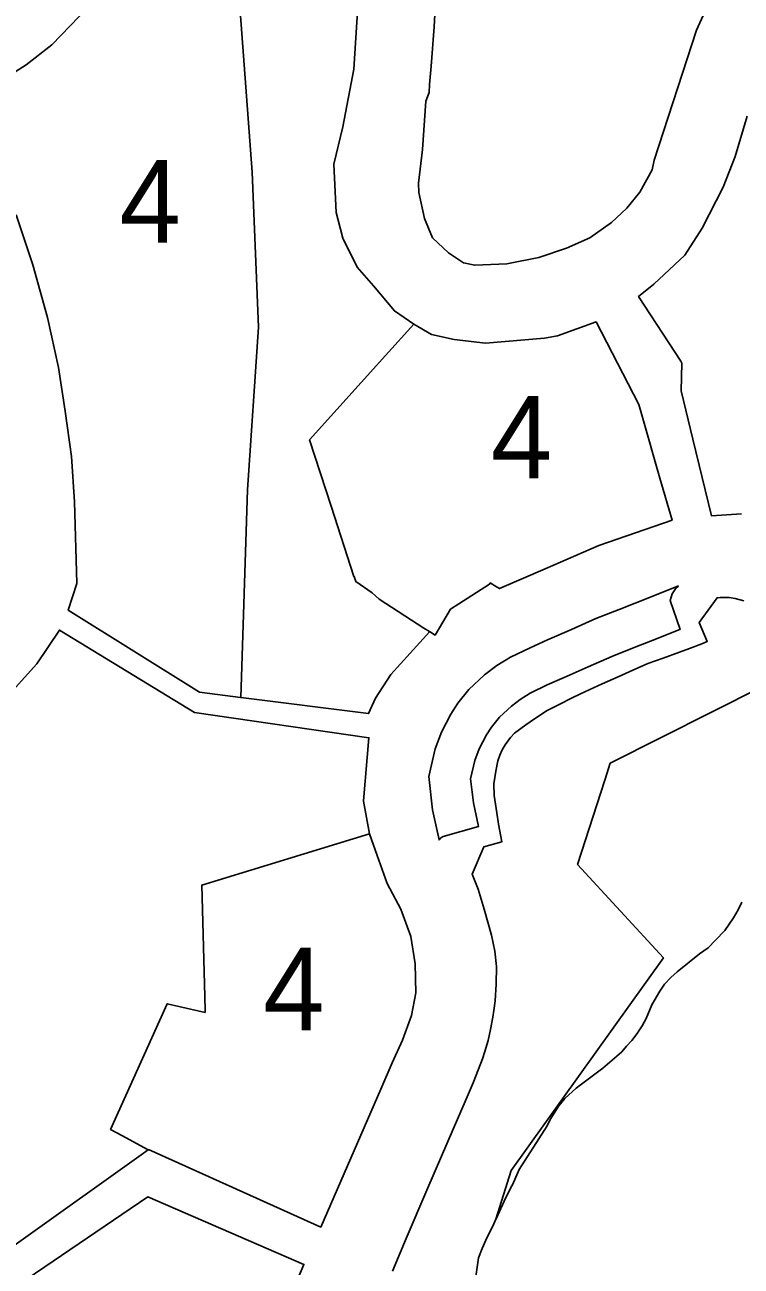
# Model space of a CAD drawing. Extents: x 598968 to 613553, y 4409678 to 4430833.
# Drawn here: x 610612.2 to 610716.3, y 4416399.9 to 4416580.3 of the extents above; entities that cross this region are included whole.
import ezdxf

# ---------------------------------------------------------------- set-up
doc = ezdxf.new("R2010")
doc.units = 0
doc.layers.add('1', color=7, linetype='Continuous')
doc.layers.add('ZONA 4. CASES UNIFAMILIRAS AÏLLADES EN PARCEL.LES', color=7, linetype='Continuous')

msp = doc.modelspace()

# ---------------------------------------------------------------- linework, layer by layer
at = {"layer": '1'}
for points in [[(610660.9172, 4416587.5407), (610660.0579, 4416573.8288), (610658.4675, 4416565.4121), (610657.1735, 4416560.0312), (610657.1748, 4416560.0035), (610657.1735, 4416559.9982), (610657.4965, 4416552.9968), (610658.4664, 4416549.2357), (610660.5543, 4416545.0335), (610662.9194, 4416542.3407), (610665.9554, 4416538.6825), (610668.7515, 4416536.7719), (610668.7939, 4416536.7578), (610671.3454, 4416535.2616), (610674.6182, 4416534.5411), (610679.1944, 4416533.987), (610687.7415, 4416534.7319), (610689.6651, 4416535.0746), (610695.254, 4416537.0816), (610701.4865, 4416525.0936), (610702.0527, 4416523.0575), (610704.5314, 4416514.3787), (610706.2986, 4416508.3056), (610695.6807, 4416504.6208), (610687.8593, 4416501.2363), (610681.2337, 4416498.3494), (610680.5348, 4416498.7445), (610680.2391, 4416498.9415), (610679.8813, 4416499.1721), (610679.7915, 4416498.984), (610675.3271, 4416496.14), (610674.0967, 4416495.355), (610671.8547, 4416491.5958), (610671.0654, 4416492.1057), (610671.0443, 4416492.0863), (610671.0281, 4416492.0685), (610665.4224, 4416485.867), (610663.2043, 4416482.4376), (610662.2097, 4416480.1888), (610643.6531, 4416482.5219), (610643.6115, 4416482.5122), (610637.6424, 4416483.3016), (610618.5505, 4416495.1884), (610618.5594, 4416495.2159), (610619.8116, 4416499.0925), (610619.8107, 4416499.1227), (610619.8116, 4416499.1255), (610619.4525, 4416510.9441), (610619.0127, 4416517.5269), (610618.1214, 4416524.1063), (610617.1325, 4416530.4638), (610615.5494, 4416537.7554), (610613.4179, 4416545.3677), (610610.9893, 4416552.6588)], [(610643.1815, 4416586.8512), (610645.2816, 4416558.8517), (610646.2116, 4416536.342), (610644.6019, 4416512.6772), (610643.6531, 4416482.5219), (610662.2097, 4416480.1888), (610663.2043, 4416482.4376), (610665.4224, 4416485.867), (610671.0281, 4416492.0685), (610671.0443, 4416492.0863), (610670.2384, 4416492.6069), (610663.7445, 4416496.8021), (610662.6969, 4416497.7491), (610660.3443, 4416499.3532), (610660.11, 4416500.0876), (610660.072, 4416500.1219), (610656.762, 4416510.3217), (610653.632, 4416519.9615), (610664.6717, 4416532.1913), (610668.7939, 4416536.7578), (610668.7515, 4416536.7719), (610665.9554, 4416538.6825), (610662.9194, 4416542.3407), (610660.5543, 4416545.0335), (610658.4664, 4416549.2357), (610657.4965, 4416552.9968), (610657.1735, 4416559.9982), (610657.1748, 4416560.0035), (610657.1735, 4416560.0312), (610658.4675, 4416565.4121), (610660.0579, 4416573.8288), (610660.9172, 4416587.5407)], [(610712.5511, 4416585.5047), (610709.8711, 4416579.4847), (610703.7213, 4416560.5849), (610703.4213, 4416559.1949), (610701.6113, 4416555.945), (610699.7413, 4416553.625), (610697.5114, 4416551.5149), (610694.3714, 4416549.3149), (610690.9815, 4416547.8049), (610686.9615, 4416546.4348), (610682.2916, 4416545.5448), (610677.6316, 4416545.3246), (610676.0117, 4416545.6947), (610673.8317, 4416547.1146), (610671.5017, 4416549.3245), (610670.3118, 4416552.1045), (610669.5217, 4416555.8744), (610669.4628, 4416557.2699), (610670.0517, 4416562.1613), (610670.5417, 4416569.1511), (610671.0117, 4416570.4011), (610671.0486, 4416571.5732), (610671.2898, 4416574.2337), (610671.7388, 4416579.965), (610671.9916, 4416584.441)], [(610610.8425, 4416573.4031), (610612.4503, 4416574.4243), (610616.1822, 4416577.3684), (610621.454, 4416582.8233)], [(610716.3773, 4416509.2172), (610712.0135, 4416508.9309), (610709.3171, 4416520.0641), (610707.6145, 4416527.0938), (610707.6137, 4416527.0974), (610707.7303, 4416531.0838), (610707.7313, 4416531.1154), (610707.5513, 4416531.3954), (610701.4241, 4416540.7873), (610703.6731, 4416542.5836), (610708.1712, 4416546.7722), (610710.6912, 4416550.6882), (610713.7487, 4416556.6722), (610715.4893, 4416561.1421), (610717.2091, 4416566.9639)], [(610665.6539, 4416399.1727), (610667.6598, 4416403.911), (610670.642, 4416410.9433), (610673.7085, 4416418.014), (610676.3563, 4416424.1472), (610677.3794, 4416426.5437), (610678.1882, 4416428.4934), (610678.746, 4416430.0328), (610679.1044, 4416431.0824), (610679.5591, 4416432.6739), (610679.9119, 4416434.2831), (610680.2504, 4416436.0944), (610680.4054, 4416437.0505), (610680.6118, 4416438.4331), (610680.7221, 4416440.878), (610680.7918, 4416443.423), (610680.7911, 4416443.4297), (610680.7918, 4416443.4561), (610680.5518, 4416445.666), (610680.0618, 4416447.9959), (610678.9792, 4416451.7511), (610678.1418, 4416454.6559), (610677.2487, 4416456.839), (610678.9418, 4416460.8127), (610681.5418, 4416461.5228), (610681.5361, 4416461.5543), (610681.5418, 4416461.5558), (610681.0822, 4416464.1295), (610680.8146, 4416465.7756), (610680.4418, 4416468.2957), (610680.4025, 4416469.9571), (610680.4018, 4416469.9857), (610680.6818, 4416471.8356), (610681.0018, 4416473.2957), (610681.2817, 4416474.1156), (610681.6317, 4416474.9056), (610682.0517, 4416475.6556), (610682.8118, 4416476.7056), (610683.4017, 4416477.3356), (610685.0517, 4416478.5656), (610686.3269, 4416479.4131), (610688.1517, 4416480.6257), (610689.9703, 4416481.5548), (610691.6754, 4416482.4261), (610692.9952, 4416483.0446), (610696.1546, 4416484.5099), (610698.4499, 4416485.5234), (610700.046, 4416486.2249), (610702.8014, 4416487.4358), (610705.0072, 4416488.2487), (610707.3931, 4416489.1278), (610708.8302, 4416489.6575), (610710.6151, 4416490.3361), (610711.4094, 4416490.6611), (610711.4213, 4416490.6659), (610710.2601, 4416493.4151), (610712.8414, 4416497.0129), (610713.2813, 4416497.0529), (610713.585, 4416497.0483), (610714.6013, 4416497.033), (610715.4713, 4416496.913), (610716.7512, 4416496.563)], [(610716.7512, 4416496.563), (610715.4713, 4416496.913), (610714.6013, 4416497.033), (610713.585, 4416497.0483), (610713.2813, 4416497.0529), (610712.8414, 4416497.0129), (610710.2601, 4416493.4151), (610711.4213, 4416490.6659), (610711.4094, 4416490.6611), (610710.6151, 4416490.3361), (610708.8302, 4416489.6575), (610707.3931, 4416489.1278), (610705.0072, 4416488.2487), (610702.8014, 4416487.4358), (610700.046, 4416486.2249), (610698.4499, 4416485.5234), (610696.1546, 4416484.5099), (610692.9952, 4416483.0446), (610691.6754, 4416482.4261), (610689.9703, 4416481.5548), (610688.1517, 4416480.6257), (610686.3269, 4416479.4131), (610685.0517, 4416478.5656), (610683.4017, 4416477.3356), (610682.8118, 4416476.7056), (610682.0517, 4416475.6556), (610681.6317, 4416474.9056), (610681.2817, 4416474.1156), (610681.0018, 4416473.2957), (610680.6818, 4416471.8356), (610680.4018, 4416469.9857), (610680.4025, 4416469.9571), (610680.4418, 4416468.2957), (610680.8146, 4416465.7756), (610681.0822, 4416464.1295), (610681.5418, 4416461.5558), (610681.5361, 4416461.5543), (610681.5418, 4416461.5228), (610678.9418, 4416460.8127), (610677.2487, 4416456.839), (610678.1418, 4416454.6559), (610678.9792, 4416451.7511), (610680.0618, 4416447.9959), (610680.5518, 4416445.666), (610680.7918, 4416443.4561), (610680.7911, 4416443.4297), (610680.7918, 4416443.423), (610680.7221, 4416440.878), (610680.6118, 4416438.4331), (610680.4054, 4416437.0505), (610680.2504, 4416436.0944), (610679.9119, 4416434.2831), (610679.5591, 4416432.6739), (610679.1044, 4416431.0824), (610678.746, 4416430.0328), (610678.1882, 4416428.4934), (610677.3794, 4416426.5437), (610676.3563, 4416424.1472), (610673.7085, 4416418.014), (610670.642, 4416410.9433), (610667.6598, 4416403.911), (610665.6539, 4416399.1727)], [(610606.8922, 4416479.5621), (610613.976, 4416487.4297), (610617.2703, 4416492.3076), (610636.9174, 4416480.3426), (610662.2397, 4416476.6803), (610661.4697, 4416467.5107), (610661.4715, 4416467.5004), (610661.4697, 4416467.4776), (610662.3547, 4416462.7144), (610663.4643, 4416459.5728), (610664.9029, 4416455.4766), (610666.869, 4416451.7398), (610668.3335, 4416447.7964), (610668.9809, 4416443.8201), (610669.0539, 4416439.5933), (610668.431, 4416436.3144), (610667.1121, 4416432.7353), (610665.6495, 4416429.4534), (610663.9713, 4416425.6122), (610655.2382, 4416405.5775), (610630.2121, 4416416.8263), (610630.1857, 4416416.8075), (610610.6941, 4416402.8965)], [(610610.6941, 4416402.8965), (610630.1857, 4416416.8075), (610626.3636, 4416418.8744), (610624.7207, 4416419.7629), (610632.953, 4416438.0103), (610634.6035, 4416437.6375), (610638.4472, 4416436.7694), (610638.4407, 4416437.0122), (610638.3849, 4416439.0961), (610637.9529, 4416455.2452), (610662.3547, 4416462.7144), (610661.4697, 4416467.4776), (610661.4715, 4416467.5004), (610661.4697, 4416467.5107), (610662.2397, 4416476.6803), (610636.9174, 4416480.3426), (610617.2703, 4416492.3076), (610613.976, 4416487.4297), (610606.8922, 4416479.5621)], [(610677.5652, 4416396.7033), (610678.1938, 4416401.1172), (610678.7038, 4416402.4671), (610679.2138, 4416403.6871), (610680.4238, 4416406.067), (610680.7089, 4416406.7096), (610682.9414, 4416413.815), (610705.0415, 4416444.7155), (610692.5699, 4416458.2357), (610696.5349, 4416470.5118), (610697.3261, 4416472.9617), (610719.4516, 4416484.1178)], [(610719.4516, 4416484.1178), (610697.3261, 4416472.9617), (610696.5349, 4416470.5118), (610692.5699, 4416458.2357), (610705.0415, 4416444.7155), (610682.9414, 4416413.815), (610680.7089, 4416406.7096), (610680.7324, 4416406.7624), (610681.8838, 4416409.357), (610682.3437, 4416410.247), (610683.0237, 4416411.567), (610683.0937, 4416411.707), (610684.0636, 4416413.937), (610688.1336, 4416420.297), (610688.6035, 4416421.207), (610689.8335, 4416423.167), (610690.6934, 4416424.237), (610692.3734, 4416425.747), (610696.2333, 4416428.6569), (610698.2532, 4416430.417), (610698.9832, 4416431.037), (610699.6832, 4416431.837), (610700.4432, 4416432.697), (610701.2332, 4416433.697), (610701.4731, 4416434.067), (610701.9531, 4416434.807), (610702.5331, 4416435.867), (610703.373, 4416437.8769), (610704.513, 4416439.8669), (610705.203, 4416440.8569), (610706.123, 4416441.8369), (610707.033, 4416442.6569), (610710.2828, 4416445.267), (610711.5428, 4416446.167), (610712.5928, 4416447.247), (610713.9628, 4416448.647), (610715.2427, 4416450.517), (610715.9027, 4416451.647), (610716.4326, 4416452.757)], [(610612.604, 4416398.0546), (610630.0997, 4416409.9695), (610652.8129, 4416400.1541), (610652.8009, 4416400.1262), (610646.0374, 4416384.2133)]]:
    msp.add_lwpolyline(points, dxfattribs=at)
for points in [[(610672.6919, 4416462.1157), (610672.4516, 4416461.8292), (610671.5059, 4416466.2126), (610670.9433, 4416471.0291), (610671.8875, 4416475.0646), (610672.8002, 4416477.5035), (610674.1693, 4416480.0772), (610675.1898, 4416481.6806), (610676.7899, 4416483.6915), (610679.0616, 4416485.8197), (610680.8132, 4416487.1681), (610682.8351, 4416488.3971), (610685.6583, 4416489.7525), (610688.1945, 4416490.8767), (610691.672, 4416492.4181), (610695.218, 4416493.9902), (610698.6006, 4416495.3186), (610700.9597, 4416496.2452), (610707.1495, 4416498.6765), (610707.2167, 4416498.7029), (610706.9114, 4416498.4328), (610706.3314, 4416497.5728), (610706.0268, 4416496.6), (610707.4614, 4416492.3859), (610707.4516, 4416492.382), (610703.1531, 4416490.6937), (610700.7939, 4416489.7671), (610697.5315, 4416488.4857), (610694.1033, 4416486.9661), (610690.6259, 4416485.4247), (610688.1727, 4416484.3372), (610685.6986, 4416483.1493), (610684.2117, 4416482.2455), (610682.9517, 4416481.2755), (610681.2117, 4416479.6456), (610680.0818, 4416478.2256), (610679.3567, 4416477.0862), (610678.2818, 4416475.0656), (610677.6418, 4416473.3556), (610677.0218, 4416470.7056), (610677.0245, 4416470.6836), (610677.4318, 4416467.1956), (610678.1718, 4416463.7657), (610678.1651, 4416463.7638), (610673.0287, 4416462.3376)], [(610672.6919, 4416462.1157), (610673.0287, 4416462.3376), (610678.1651, 4416463.7638), (610678.1718, 4416463.7657), (610677.4318, 4416467.1956), (610677.0245, 4416470.6836), (610677.0218, 4416470.7056), (610677.6418, 4416473.3556), (610678.2818, 4416475.0656), (610679.3567, 4416477.0862), (610680.0818, 4416478.2256), (610681.2117, 4416479.6456), (610682.9517, 4416481.2755), (610684.2117, 4416482.2455), (610685.6986, 4416483.1493), (610688.1727, 4416484.3372), (610690.6259, 4416485.4247), (610694.1033, 4416486.9661), (610697.5315, 4416488.4857), (610700.7939, 4416489.7671), (610703.1531, 4416490.6937), (610707.4516, 4416492.382), (610707.4614, 4416492.3859), (610706.0268, 4416496.6), (610706.3314, 4416497.5728), (610706.9114, 4416498.4328), (610707.2167, 4416498.7029), (610707.1495, 4416498.6765), (610700.9597, 4416496.2452), (610698.6006, 4416495.3186), (610695.218, 4416493.9902), (610691.672, 4416492.4181), (610688.1945, 4416490.8767), (610685.6583, 4416489.7525), (610682.8351, 4416488.3971), (610680.8132, 4416487.1681), (610679.0616, 4416485.8197), (610676.7899, 4416483.6915), (610675.1898, 4416481.6806), (610674.1693, 4416480.0772), (610672.8002, 4416477.5035), (610671.8875, 4416475.0646), (610670.9433, 4416471.0291), (610671.5059, 4416466.2126), (610672.4516, 4416461.8292)]]:
    msp.add_lwpolyline(points, close=True, dxfattribs=at)
at = {"layer": 'ZONA 4. CASES UNIFAMILIRAS AÏLLADES EN PARCEL.LES'}
for points in [[(610610.9893, 4416552.6588), (610613.4179, 4416545.3677), (610615.5494, 4416537.7554), (610617.1325, 4416530.4638), (610618.1214, 4416524.1063), (610619.0127, 4416517.5269), (610619.4525, 4416510.9441), (610619.8116, 4416499.1255), (610619.8107, 4416499.1227), (610619.8116, 4416499.0925), (610618.5594, 4416495.2159), (610618.5505, 4416495.1884), (610637.6424, 4416483.3016), (610643.6115, 4416482.5122), (610643.6531, 4416482.5219), (610644.6019, 4416512.6772), (610646.2116, 4416536.342), (610645.2816, 4416558.8517), (610643.1815, 4416586.8512)], [(610671.9916, 4416584.441), (610671.7388, 4416579.965), (610671.2898, 4416574.2337), (610671.0486, 4416571.5732), (610671.0117, 4416570.4011), (610670.5417, 4416569.1511), (610670.0517, 4416562.1613), (610669.4628, 4416557.2699), (610669.5217, 4416555.8744), (610670.3118, 4416552.1045), (610671.5017, 4416549.3245), (610673.8317, 4416547.1146), (610676.0117, 4416545.6947), (610677.6316, 4416545.3246), (610682.2916, 4416545.5448), (610686.9615, 4416546.4348), (610690.9815, 4416547.8049), (610694.3714, 4416549.3149), (610697.5114, 4416551.5149), (610699.7413, 4416553.625), (610701.6113, 4416555.945), (610703.4213, 4416559.1949), (610703.7213, 4416560.5849), (610709.8711, 4416579.4847), (610712.5511, 4416585.5047)], [(610621.454, 4416582.8233), (610616.1822, 4416577.3684), (610612.4503, 4416574.4243), (610610.8425, 4416573.4031)], [(610717.2091, 4416566.9639), (610715.4893, 4416561.1421), (610713.7487, 4416556.6722), (610710.6912, 4416550.6882), (610708.1712, 4416546.7722), (610703.6731, 4416542.5836), (610701.4241, 4416540.7873), (610707.5513, 4416531.3954), (610707.7313, 4416531.1154), (610707.7303, 4416531.0838), (610707.6137, 4416527.0974), (610707.6145, 4416527.0938), (610709.3171, 4416520.0641), (610712.0135, 4416508.9309), (610716.3773, 4416509.2172)], [(610646.0374, 4416384.2133), (610652.8009, 4416400.1262), (610652.8129, 4416400.1541), (610630.0997, 4416409.9695), (610612.604, 4416398.0546)]]:
    msp.add_lwpolyline(points, dxfattribs=at)
for points in [[(610671.0443, 4416492.0863), (610671.0654, 4416492.1057), (610671.8547, 4416491.5958), (610674.0967, 4416495.355), (610675.3271, 4416496.14), (610679.7915, 4416498.984), (610679.8813, 4416499.1721), (610680.2391, 4416498.9415), (610680.5348, 4416498.7445), (610681.2337, 4416498.3494), (610687.8593, 4416501.2363), (610695.6807, 4416504.6208), (610706.2986, 4416508.3056), (610704.5314, 4416514.3787), (610702.0527, 4416523.0575), (610701.4865, 4416525.0936), (610695.254, 4416537.0816), (610689.6651, 4416535.0746), (610687.7415, 4416534.7319), (610679.1944, 4416533.987), (610674.6182, 4416534.5411), (610671.3454, 4416535.2616), (610668.7939, 4416536.7578), (610664.6717, 4416532.1913), (610653.632, 4416519.9615), (610656.762, 4416510.3217), (610660.072, 4416500.1219), (610660.11, 4416500.0876), (610660.3443, 4416499.3532), (610662.6969, 4416497.7491), (610663.7445, 4416496.8021), (610670.2384, 4416492.6069)], [(610630.1857, 4416416.8075), (610630.2121, 4416416.8263), (610655.2382, 4416405.5775), (610663.9713, 4416425.6122), (610665.6495, 4416429.4534), (610667.1121, 4416432.7353), (610668.431, 4416436.3144), (610669.0539, 4416439.5933), (610668.9809, 4416443.8201), (610668.3335, 4416447.7964), (610666.869, 4416451.7398), (610664.9029, 4416455.4766), (610663.4643, 4416459.5728), (610662.3547, 4416462.7144), (610637.9529, 4416455.2452), (610638.3849, 4416439.0961), (610638.4407, 4416437.0122), (610638.4472, 4416436.7694), (610634.6035, 4416437.6375), (610632.953, 4416438.0103), (610624.7207, 4416419.7629), (610626.3636, 4416418.8744)]]:
    msp.add_lwpolyline(points, close=True, dxfattribs=at)

# ---------------------------------------------------------------- texts
for p in [(610626.0049, 4416548.6247), (610679.9653, 4416514.3387), (610646.8873, 4416434.146)]:
    msp.add_text('4', height=12, dxfattribs=at).set_placement(p)

doc.saveas('drawing.dxf')
